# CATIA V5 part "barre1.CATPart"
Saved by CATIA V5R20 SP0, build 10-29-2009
Part number: barre1
Bounding box of the stored display mesh (mm): x -10 to 0, y -24.999 to 110.005, z -46.188 to 25
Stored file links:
  D:\Dropbox\IAO_2012\IAO_2012_748_omeyer\omeyer\omeyer\barre1.CATPart
  U:\Projet IAO\omeyer\Catia\Ass_748_skl.CATProduct
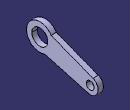
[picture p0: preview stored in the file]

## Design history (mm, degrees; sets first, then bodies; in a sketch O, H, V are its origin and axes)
Set1
  Plane1 "PlanRef": linked copy from another document
  Point1 "PointB": linked copy from another document
  Point2 "PointA": linked copy from another document
  Point3 "PointA": linked copy from another document
Body1 (main body)
  Sketch1 on Plane1, origin (0, 0, 0), H (0, 1, 0), V (0, 0, 1)
    arc A1 centre (95.0111, -31.1913) radius 15 from (91.0508, -45.6591) to (100.3965, -17.1914) ccw
    point P1 (95.0111, -31.1913)
    arc A2 centre (0, 0) radius 25 from (21.1805, 13.2811) to (9.1874, -23.2506) ccw
    point P2 (0, 0)
    reference projected point E1 (95.0111, -31.1913) from Point1
    reference projected point E2 (0, 0) from Point2
    line L1 (91.0508, -45.6591) -> (9.1874, -23.2506)
    line L2 (100.3965, -17.1914) -> (21.1805, 13.2811)
    reference projected point E3 (0, 0) from Point3
    reference projected point E4 (0, 0) from Point3
    circle A3 centre (95.0111, -31.1913) radius 7.5
    point P7 (95.0111, -31.1913)
    circle A4 centre (0, 0) radius 15
    point P8 (0, 0)
    reference projected point E5 (0, 0) from Point2
    reference projected point E6 (95.0111, -31.1913) from Point1
    radius A1 = 15
    radius A2 = 25
    distance L2 E3 = 20
    distance E4 L1 = 20
    radius A3 = 7.5
    radius A4 = 15
    coincidence: P1 E1, P2 E2, P8 E5, P7 E6
    tangency: L1 A1, L2 A1
  Pad1: profile Sketch1, direction (-1, 0, 0), length 10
